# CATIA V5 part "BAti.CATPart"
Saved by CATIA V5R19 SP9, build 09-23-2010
Part number: BAti
Bounding box of the stored display mesh (mm): x -67.792 to 40, y -79.914 to 79.914, z -79.981 to 79.981
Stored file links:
  Y:\projet be 2011-12\Etude cinématique\BAti.CATPart
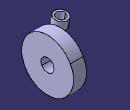
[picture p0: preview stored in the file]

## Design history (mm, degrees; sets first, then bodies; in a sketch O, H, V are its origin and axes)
Body1 (main body)
  Sketch1 on xy-plane, origin (0, 0, 0), H (1, 0, 0), V (0, 1, 0)
    line L1 (0, 80) -> (40, 80)
    line L2 (40, 80) -> (40, 20)
    line L3 (40, 20) -> (0, 20)
    line L4 (0, 20) -> (0, 80)
    length L3 = 40
    distance H L3 = 20
    distance H L1 = 80
    horizontal: L1 H, L3 H
    vertical: L2 V, L4 V
    coincidence: L4 V
  Shaft1: profile Sketch1, axis Sketch1.H, angle 360
  DatumCurve1
  DatumSurface1
  Sketch2 on face of Shaft1 from Sketch1.L4, origin (0, 0, 0), H (0, -1, 0), V (0, 0, 1)
    circle A1 centre (0, -52) radius 12.1169
    reference projected arc E1 centre (0, -52) radius 12 from (1.2623, -63.9334) to (1.2623, -40.0666) ccw from edge of DatumCurve1
    concentricity: A1 E1
  Pad1: profile Sketch2, direction (-1, 0, 0), length 62
  DatumSurface2
  Plane1: type Offset, RefPlane DatumSurface2, Offset 10
  DatumSurface3
  Sketch3 on Plane1, origin (-47.7977, 0, 0), H (0, 1, 0), V (0, 0, 1)
    point P1 (0, -52)
    line L1 (19.8312, -52) -> (-193.8327, -52)
    line L2 (-67, -77.3341) -> (-67, 34.5276)
    distance L1 H = 52
    distance P1 L2 = 67
    coincidence: P1 V, P1 L1
    horizontal: L1 H
    vertical: L2 V
  Sketch4 on Plane1, origin (-47.7977, 0, 0), H (0, 1, 0), V (0, 0, 1)
    line L1 (-67, -52) -> (-49.9162, 44.8871)
    point P1 (-67, -52)
    reference projected line E1 (19.8312, -52) -> (-193.8327, -52) from Sketch3.L1
    reference projected line E2 (-67, -77.3341) -> (-67, 34.5276) from Sketch3.L2
    reference projected line E3 (-67, -77.3341) -> (-67, 34.5276) from Sketch3.L2
    angle L1 E3 = 10
    coincidence: P1 E1, P1 E2
  Sketch5 on Plane1, origin (-47.7977, 0, 0), H (0, 1, 0), V (0, 0, 1)
    line L1 (-46.3377, 65.1817) -> (-66.0339, 68.6547)
    line L2 (-66.0339, 68.6547) -> (-70.972, 40.6491)
    line L3 (-70.972, 40.6491) -> (-51.2758, 37.1762)
    line L4 (-51.2758, 37.1762) -> (-46.3377, 65.1817)
    reference projected line E1 (-67, -52) -> (-49.9162, 44.8871) from Sketch4
    distance L4 L2 = 20
    coincidence: L4 E1
    perpendicularity: L4 L1, L3 L4
  Shaft2: profile Sketch5, axis Sketch4.L1, angle 360
  Sketch6 on face of Shaft2 from Sketch5.L1, origin (0, 9.7495, 55.2921), H (-1, 0, 0), V (0, -0.9848, 0.1736)
    circle A1 centre (47.7977, 56.9524) radius 14
    reference projected circle E1 centre (47.7977, 56.9524) radius 20 from edge [face of Shaft2 from Sketch5.L2 | face of Shaft2 from Sketch5.L1]
    radius A1 = 14
    concentricity: E1 A1
  Pocket1: profile Sketch6, direction (0, -0.1736, -0.9848), length 62
  Sketch7 on face of Shaft1 from Sketch1.L4, origin (0, 0, 0), H (0, -1, 0), V (0, 0, 1)
    circle A1 centre (50.2281, 45.9217) radius 3.6847
  Pad2: profile Sketch7, direction (-1, 0, 0), up to face of Shaft2 from Sketch5.L2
